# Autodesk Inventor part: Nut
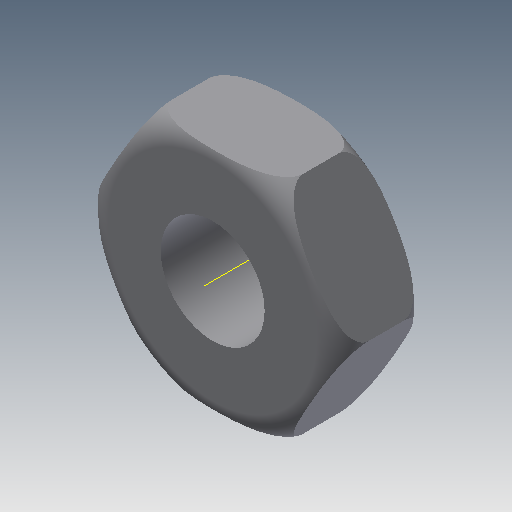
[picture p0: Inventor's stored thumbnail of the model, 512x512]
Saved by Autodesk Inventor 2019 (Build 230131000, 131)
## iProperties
Created: 2009-04
Part Number: Nut
Document SubType Name: Modeling
Designer: Sham
Density: 1 g/cm^3
Material: Generic
Appearance: Default
Author: Sham
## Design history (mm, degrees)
sketch "Sketch1"
  geometry: L1 (7.5, 12.99)-(15, 0); L2 (15, 0)-(7.5, -12.99); L3 (7.5, -12.99)-(-7.5, -12.99); L4 (-7.5, -12.99)-(-15, 0); L5 (-15, 0)-(-7.5, 12.99); L6 (-7.5, 12.99)-(7.5, 12.99); C1 r 6 at (0, 0); 1 further point
  constraints: 12 end point, 1 centre point, 1 coincident, 13 other
  dimensions: "d0" = 30 distance of L1.end L4.end; "d1" = 12 diameter of C1
extrude "Extrusion1" new body sketch "Sketch1" distance "d2" = 12; taper "d3" = 0 deg
sketch "Sketch2"
  geometry: L1 (-12, 0)-(-12, -0.022); L2 (-15, 7)-(-15, 3); L3 (0, -2.87)-(0, 12.87) reference; A1 r 3 centre (-12, 7) between (-12, 10) and (-15, 7); A2 r 3 centre (-12, 3) between (-15, 3) and (-12, 0)
  constraints: 4 end point, 4 point on circle, 2 centre point, 1 tangent
revolve "Revolution1" sketch "Sketch2" stored, may be unused: angle "d7" = 90 deg
body "Solid1"
other parameters: "d6" = 90 deg
